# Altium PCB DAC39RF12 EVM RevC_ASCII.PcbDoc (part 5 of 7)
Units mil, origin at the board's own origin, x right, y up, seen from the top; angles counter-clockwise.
Board outline 5071.81 x 2716.54 mil, 16 copper layers (Top Layer, L2 GND1, L3 PWR1, L4 GND2, L5 PWR2, L6 GND3, L7 Ctrl Signal 1, L8 GND4, L9 GND5, L10 Ctrl Signal 2, L11 GND6, L12 PWR3, L13 GND7, L14 PWR4, L15 GND8, Bottom Layer), stack 82.4 mil thick; 596 components, 375 nets, 3310 pads, 1662 vias.
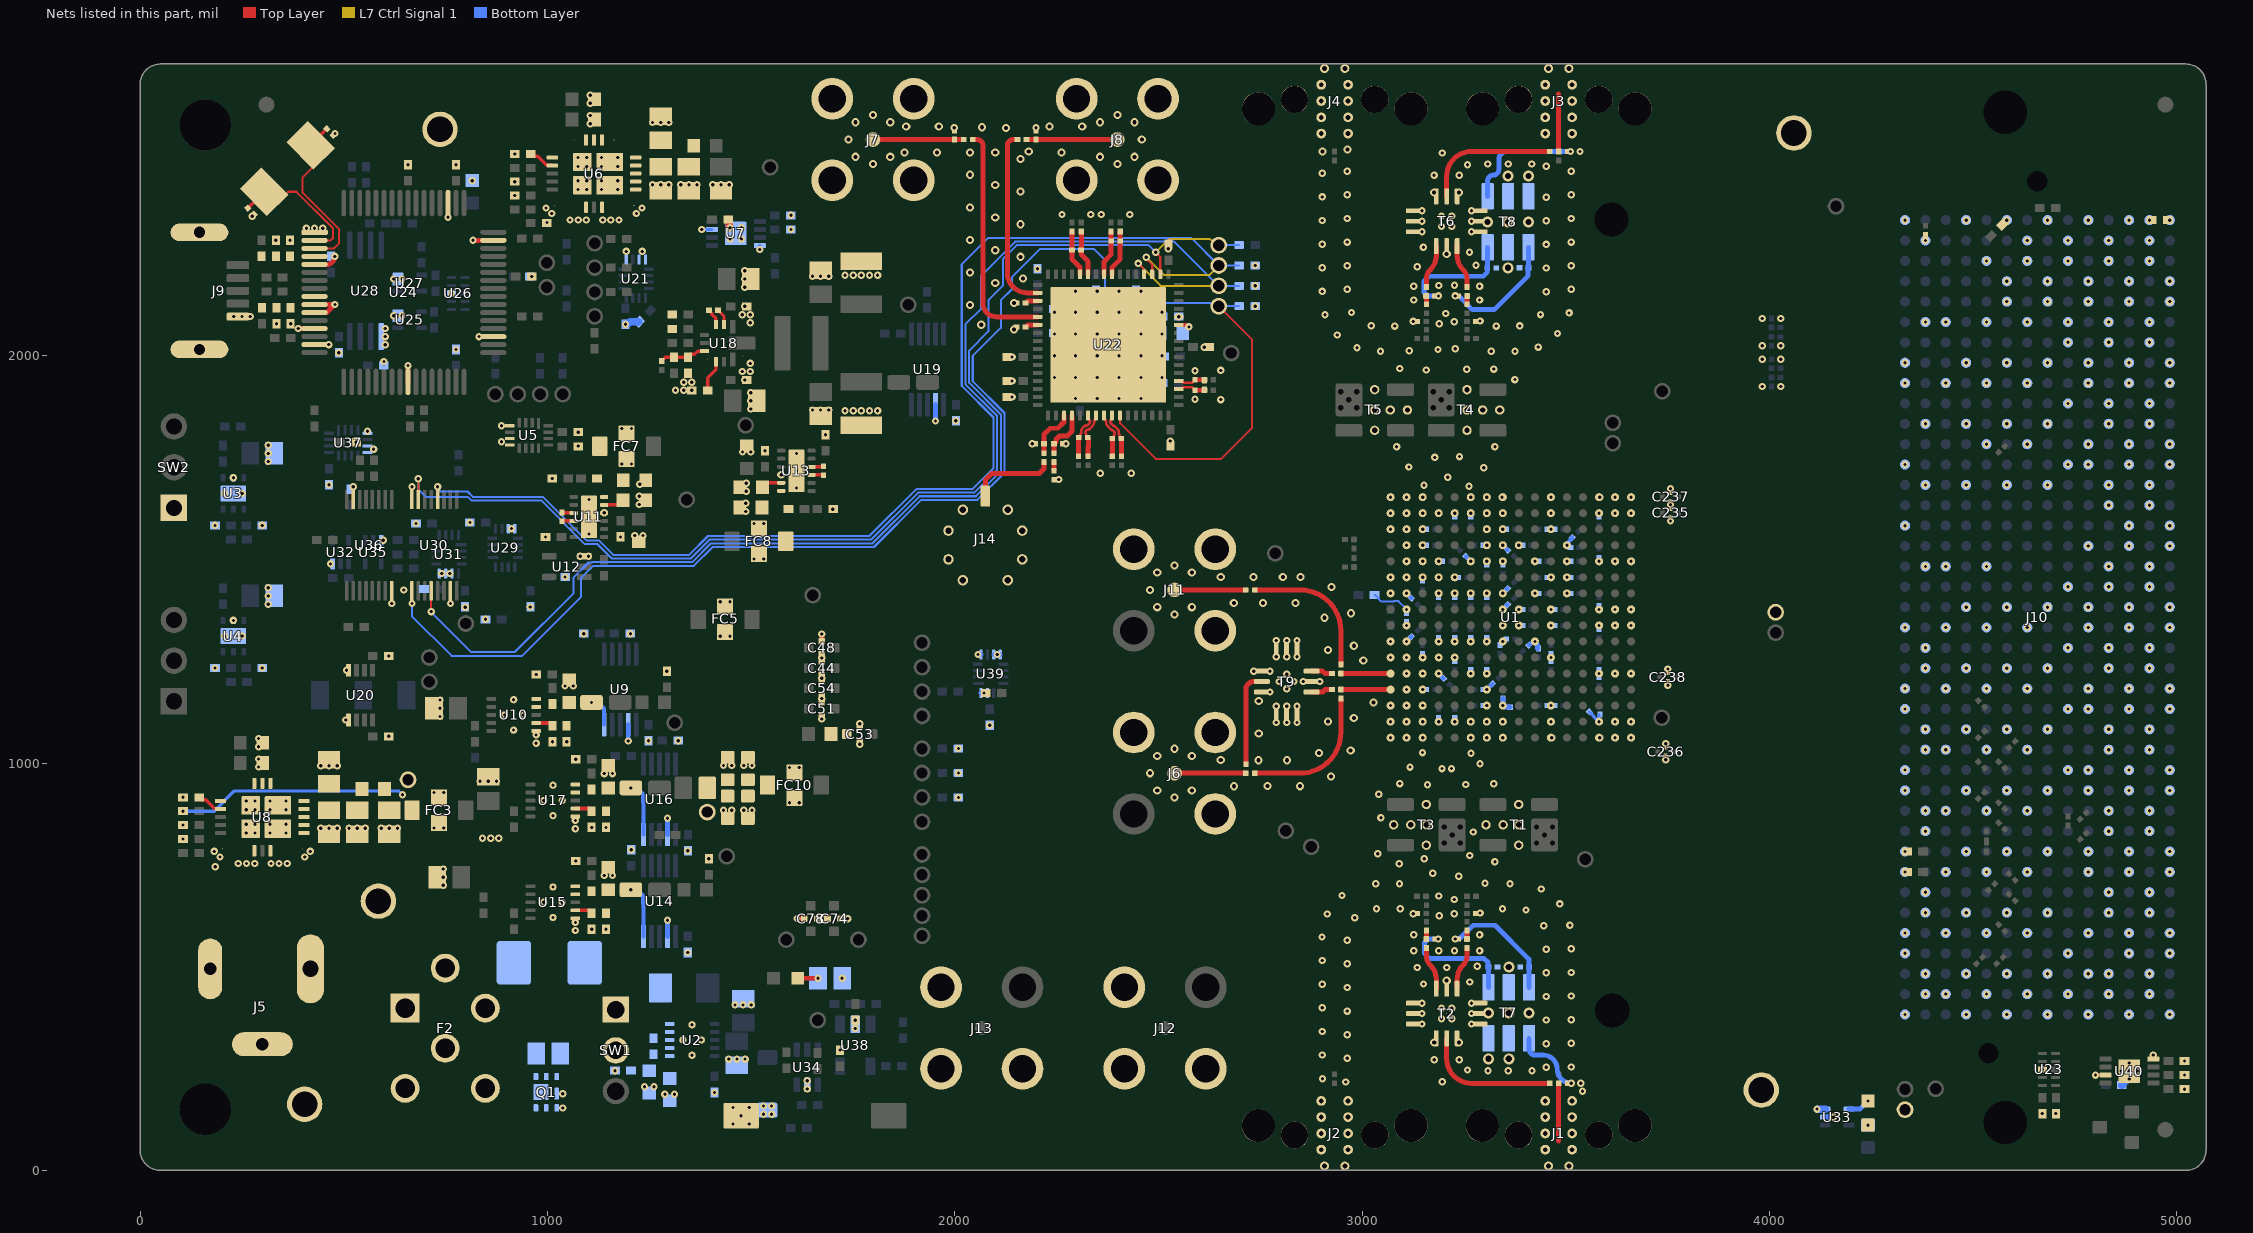
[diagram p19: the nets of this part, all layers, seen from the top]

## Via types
v1: diameter 18, hole 8, Top Layer to Bottom Layer, tented both sides, 1558 vias
v2: diameter 20, hole 10, Top Layer to Bottom Layer, tented both sides, 92 vias
v3: diameter 27, hole 15, Top Layer to Bottom Layer, tented both sides, 12 vias

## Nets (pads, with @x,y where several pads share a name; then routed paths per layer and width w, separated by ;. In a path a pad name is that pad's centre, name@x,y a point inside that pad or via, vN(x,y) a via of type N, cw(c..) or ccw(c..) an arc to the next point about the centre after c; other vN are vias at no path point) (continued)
GND: "J1. "@3350.94,93.75 "J1. "@3482.6,86.25 "J1. "@3614.26,93.75 "J2. "@2800.94,93.75 "J2. "@2932.6,86.25 "J2. "@3064.27,93.75 "J3. "@3350.94,2622.78 "J3. "@3482.6,2630.28 "J3. "@3614.26,2622.78 "J4. "@2800.94,2622.78 "J4. "@2932.6,2630.28 "J4. "@3064.26,2622.78 "J14. " "T1. " "T2. " "T3. " "T4. " "T5. " "T6. " "T9. " "U2. " "U6. "@1016.37,2369.07 "U6. "@1065.09,2364.65 "U6. "@1163.51,2364.65 "U6. "@1212.24,2369.07 "U8. "@202.01,789.43 "U8. "@250.73,785 "U8. "@349.16,785 "U8. "@397.88,789.43 "U10. " "U15. " "U17. " "U18. "@1393.5,1992.3 "U18. "@1479.62,1999.68 "U18. "@1479.62,2062.68 C8.1 C9.1 C10.1 C11.1 C12.1 C13.1 C14.1 C15.1 C16.2 C18.2 C19.1 C20.1 C21.2 C23.1 C24.1 C25.1 C26.1 C27.1 C28.2 C29.1 C30.1 C33.1 C34.1 C35.1 C36.1 C37.1 C38.1 C39.1 C40.1 C41.1 C42.2 C44.2 C45.1 C46.1 C47.1 C48.2 C49.1 C50.1 C51.2 C53.2 C54.2 C55.2 C56.1 C57.1 C59.1 C63.1 C64.1 C65.1 C67.1 C68.1 C69.1 C70.1 C71.1 C72.2 C73.2 C74.2 C75.1 C76.1 C78.2 C79.1 C80.2 C82.1 C83.1 C84.1 C85.1 C86.1 C87.1 C88.1 C89.1 C91.1 C92.1 C93.1 C94.1 C95.2 C96.1 C97.1 C98.1 C108.1 C109.1 C110.1 C111.1 C115.1 C116.1 C117.1 C118.1 C119.1 C120.1 C121.1 C122.1 C123.1 C124.1 C125.1 C126.1 C127.1 C128.1 C144.1 C145.1 C146.1 C147.1 C148.1 C149.1 C150.1 C151.1 C152.1 C153.1 C154.1 C155.2 C158.1 C159.1 C160.1 C161.2 C162.1 C163.1 C164.1 C165.1 C167.2 C168.2 C169.1 C170.1 C171.1 C172.2 C173.1 C174.1 C175.1 C176.1 C177.1 C178.1 C179.1 C180.1 C181.1 C182.1 C183.1 C184.1 C185.1 C186.1 C187.1 C188.1 C189.1 C190.1 C191.1 C192.1 C193.1 C194.1 C195.1 C196.2 C197.2 C198.2 C199.2 C200.2 C201.2 C202.1 C203.1 C204.1 C205.1 C206.1 C207.1 C208.1 C209.1 C210.1 C211.1 C212.1 C213.1 C214.1 C215.1 C216.1 C217.1 C218.1 C219.2 C220.2 C221.2 C222.2 C223.2 C224.2 C225.1 C226.1 C227.1 C228.1 C229.1 C230.1 C231.1 C232.1 C233.1 C234.1 C235.2 C236.2 C237.2 C238.2 C239.1 C240.1 C241.1 C242.1 C243.1 C244.1 C245.1 D1.2 FC3.2 FC5.2 FC7.2 FC8.2 FC10.2 J1.2 J1.3 J1.4 J2.2 J2.3 J2.4 J3.2 J3.3 J3.4 J4.2 J4.3 J4.4 J6.2 J6.3 J6.4 J7.2 J7.3 J7.4 J7.5 J8.2 J8.3 J8.4 J8.5 J9.5 J9.S1 J9.S2 J10.A1 J10.A4 J10.A5 J10.A8 J10.A9 J10.A12 J10.A13 J10.A16 J10.A17 J10.A20 J10.A21 J10.A24 J10.A25 J10.A28 J10.A29 J10.A32 J10.A33 J10.A36 J10.A37 J10.A40 J10.B2 J10.B3 J10.B6 J10.B7 J10.B10 J10.B11 J10.B14 J10.B15 J10.B18 J10.B19 J10.B22 J10.B23 J10.B26 J10.B27 J10.B30 J10.B31 J10.B34 J10.B35 J10.B38 J10.B39 J10.C1 J10.C4 J10.C5 J10.C8 J10.C9 J10.C12 J10.C13 J10.C17 J10.C20 J10.C21 J10.C24 J10.C25 J10.C28 J10.C29 J10.C32 J10.C33 J10.C36 J10.C38 J10.C40 J10.D2 J10.D3 J10.D6 J10.D7 J10.D10 J10.D13 J10.D19 J10.D22 J10.D25 J10.D28 J10.D37 J10.D39 J10.E1 J10.E4 J10.E5 J10.E8 J10.E11 J10.E14 J10.E20 J10.E23 J10.E26 J10.E29 J10.E32 J10.E35 J10.E38 J10.E40 J10.F2 J10.F3 J10.F6 J10.F9 J10.F12 J10.F21 J10.F24 J10.F27 J10.F30 J10.F33 J10.F36 J10.F39 J10.G1 J10.G4 J10.G5 J10.G8 J10.G11 J10.G14 J10.G20 J10.G23 J10.G26 J10.G29 J10.G32 J10.G35 J10.G38 J10.G40 J10.H3 J10.H6 J10.H9 J10.H12 J10.H18 J10.H21 J10.H24 J10.H27 J10.H30 J10.H33 J10.H36 J10.H39 J10.J1 J10.J8 J10.J11 J10.J14 J10.J20 J10.J23 J10.J26 J10.J29 J10.J32 J10.J35 J10.J38 J10.J40 J10.K6 J10.K9 J10.K18 J10.K21 J10.K24 J10.K27 J10.K30 J10.K33 J10.K36 J10.K39 J10.L2 J10.L6 J10.L11 J10.L14 J10.L18 J10.L22 J10.L23 J10.L26 J10.L27 J10.L30 J10.L31 J10.L34 J10.L35 J10.L38 J10.L39 J10.M1 J10.M8 J10.M9 J10.M13 J10.M16 J10.M21 J10.M24 J10.M25 J10.M28 J10.M29 J10.M32 J10.M33 J10.M36 J10.M37 J10.M40 J10.Y1 J10.Y4 J10.Y5 J10.Y8 J10.Y9 J10.Y12 J10.Y13 J10.Y16 J10.Y17 J10.Y20 J10.Y21 J10.Y24 J10.Y25 J10.Y28 J10.Y29 J10.Y32 J10.Y33 J10.Y36 J10.Y37 J10.Y40 J10.Z2 J10.Z3 J10.Z6 J10.Z7 J10.Z10 J10.Z11 J10.Z14 J10.Z15 J10.Z18 J10.Z19 J10.Z22 J10.Z23 J10.Z26 J10.Z27 J10.Z30 J10.Z31 J10.Z34 J10.Z35 J10.Z38 J10.Z39 J11.2 J11.3 J11.4 J12.2 J12.3 J12.4 J13.2 J13.3 J13.4 J14.2 PP2.1 PP49.1 Q1.4 Q1.7 R7.1 R8.1 R17.1 R18.1 R22.1 R23.1 R24.1 R27.2 R32.1 R33.1 R34.1 R37.1 R38.1 R40.1 R41.1 R42.1 R43.1 R49.1 R50.1 R51.1 R52.1 R56.1 R57.1 R60.1 R61.1 R63.1 R65.1 R66.1 R68.1 R73.1 R74.1 R75.1 R78.1 R81.1 R82.1 R88.1 R89.1 R90.1 R91.1 R95.1 R103.1 R104.1 R112.1 R113.1 R126.1 R148.1 R155.1 R173.1 R174.1 R175.1 R178.1 R179.1 R180.1 R181.1 R183.2 R184.2 R185.2 R188.2 R189.2 R190.2 SW2.3 SW3.2 T1.5 T2.2 T2.4 T2.5 T2.6 T2.7 T2.9 T2.10 T2.11 T2.12 T3.5 T4.5 T5.5 T6.2 T6.4 T6.5 T6.6 T6.7 T6.9 T6.10 T6.11 T6.12 T7.1 T7.2 T7.5 T8.1 T8.2 T8.5 T9.2 T9.4 T9.5 T9.6 T9.7 T9.9 T9.10 T9.11 T9.12 TP1.1 TP2.1 TP3.1 U1.A1 U1.A2 U1.A3 U1.A6 U1.A9 U1.A10 U1.A11 U1.A14 U1.A15 U1.A16 U1.B1 U1.B2 U1.B3 U1.B6 U1.B9 U1.B10 U1.B11 U1.B12 U1.B13 U1.B14 U1.B15 U1.B16 U1.C6 U1.C9 U1.C10 U1.C14 U1.C15 U1.C16 U1.D10 U1.D14 U1.D15 U1.E1 U1.E2 U1.E3 U1.E10 U1.E11 U1.E13 U1.E14 U1.E15 U1.F6 U1.F12 U1.F13 U1.F14 U1.F15 U1.F16 U1.G7 U1.G9 U1.G10 U1.G11 U1.G12 U1.G13 U1.G15 U1.G16 U1.H1 U1.H2 U1.H3 U1.H6 U1.H8 U1.H9 U1.H15 U1.J1 U1.J2 U1.J3 U1.J6 U1.J8 U1.J9 U1.K5 U1.K7 U1.K9 U1.K10 U1.K11 U1.K12 U1.K13 U1.K15 U1.K16 U1.L5 U1.L6 U1.L12 U1.L13 U1.L14 U1.L15 U1.L16 U1.M1 U1.M2 U1.M3 U1.M5 U1.M7 U1.M9 U1.M10 U1.M11 U1.M13 U1.M14 U1.M15 U1.N5 U1.N8 U1.N9 U1.N10 U1.N14 U1.N15 U1.P6 U1.P9 U1.P10 U1.P14 U1.P15 U1.P16 U1.R1 U1.R2 U1.R3 U1.R6 U1.R9 U1.R10 U1.R11 U1.R12 U1.R13 U1.R14 U1.R15 U1.R16 U1.T1 U1.T2 U1.T3 U1.T6 U1.T9 U1.T10 U1.T11 U1.T14 U1.T15 U1.T16 U2.11 U3.5 U3.7@207.31,1662.04 U3.7@228.97,1662.04 U3.7@250.62,1662.04 U4.5 U4.7@207.31,1312.04 U4.7@228.97,1312.04 U4.7@250.62,1312.04 U5.5 U5.7 U5.8 U6.3 U6.5 U6.8 U6.9 U6.16 U6.17 U6.20 U6.25 U6.26 U6.28 U7.4 U7.7 U7.9 U8.3 U8.5 U8.8 U8.9 U8.16 U8.17 U8.20 U8.25 U8.26 U8.28 U9.7 U10.6 U10.11 U11.4 U11.13 U12.3 U13.4 U13.13 U14.7 U15.6 U15.11 U16.7 U17.6 U17.11 U19.7 U20.4 U20.5 U21.5 U21.7 U21.8 U22.65 U23.3@4669.81,247.98 U24.1 U24.5 U24.10 U24.11 U24.13 U24.15 U24.25 U24.35 U24.47 U24.51 U25.2 U25.3 U26.3@764.51,2153.25 U27.2 U27.3 U28.5 U29.7 U29.8 U30.8 U30.15 U31.6 U31.7 U31.8 U32.3 U33.2 U33.3 U34.2 U35.3 U36.8 U36.15 U37.5 U37.7 U37.8 U38.2 U39.5 U39.7 U39.8 U39.15 U39.16 U40.4 U40.7 U40.9 | length 3132.7
  Top Layer w5: v1(617.53,1392.03) U36.8@617.53,1423.03 ; U30.8@667.29,1647.44 v1(667.29,1678.44) ; v1(755.91,2339.97) U24.51@755.91,2374.5 ; v1(761.78,1392.03) U30.15@761.78,1423.03 ; v1(832.13,2047.21) U24.35@866.66,2047.21
  Top Layer w8: v1(290.85,990.35) C30.1@300.85,1000.35 v1(290.85,1010.35) ; v1(290.85,1040.35) C33.1@300.85,1050.35 v1(290.85,1060.35) ; U36.15@523.04,1647.44 v1(523.04,1678.44) ; v1(1105.21,2570) C19.1@1115.21,2580 v1(1105.21,2590) ; v1(1105.21,2620) C29.1@1115.21,2630 v1(1105.21,2640) ; v1(1139.61,724.33) 1139.61,734.33 C75.1@1149.61,744.33 1159.61,734.33 v1(1159.61,724.33) ; v1(1139.61,974.33) 1139.61,984.33 C82.1@1149.61,994.33 1159.61,984.33 v1(1159.61,974.33) ; v2(2144.93,2064.27) 2148.37,2067.72 2148.37,2068.66 2148.9,2068.66 C127.1@2151.2,2070.96 ; v2(2144.93,2129.71) 2150.89,2129.71 C128.1@2151.2,2130.02 ; v1(2189.94,1784.07) R37.1@2197.03,1784.07 ; R91.1@2243.6,1695.98 2243.85,1696.23 2254.67,1696.23 v1(2254.91,1696.47) ; R38.1@2265.65,1784.07 v1(2272.73,1784.07) ; v1(2733.67,1225.9) T9.7@2753.67,1225.9 v1(2773.67,1225.9) ; T9.9@2753.67,1174.72 v1(2773.67,1174.72) ; v1(2789.1,1099.6) T9.10@2789.1,1119.6 v1(2789.1,1139.6) ; v1(2789.1,1261.02) T9.6@2789.1,1281.02 v1(2789.1,1301.02) ; v1(2814.69,1099.6) T9.11@2814.69,1119.6 v1(2814.69,1139.6) ; v1(2814.69,1261.02) T9.5@2814.69,1281.02 v1(2814.69,1301.02) ; v1(2840.28,1099.6) T9.12@2840.28,1119.6 v1(2840.28,1139.6) ; v1(2840.28,1261.02) T9.4@2840.28,1281.02 v1(2840.28,1301.02) ; v1(2855.71,1200.31) T9.2@2875.71,1200.31 v1(2895.71,1200.31) ; T2.6@3126.89,359.67 v1(3146.89,359.67) ; T2.5@3126.89,385.26 v1(3146.89,385.26) ; T2.4@3126.89,410.85 v1(3146.89,410.85) ; T6.12@3126.89,2304.73 v1(3146.89,2304.73) ; T6.11@3126.89,2330.32 v1(3146.89,2330.32) ; T6.10@3126.89,2355.91 v1(3146.89,2355.91) ; v2(3176.88,2401.34) T6.9@3181.88,2401.34 ; v2(3177.01,314.23) T2.7@3182.01,314.23 ; T2.2@3207.6,446.28 v2(3207.6,465.97) ; v2(3207.6,2249.61) T6.2@3207.6,2269.3 ; T6.7@3233.06,2401.34 v2(3238.06,2401.34) ; T2.9@3233.19,314.23 v2(3238.19,314.23) ; v1(3268.31,359.67) T2.10@3288.31,359.67 ; v1(3268.31,385.26) T2.11@3288.31,385.26 ; v1(3268.31,410.85) T2.12@3288.31,410.85 ; v1(3268.31,2304.73) T6.4@3288.31,2304.73 ; v1(3268.31,2330.32) T6.5@3288.31,2330.32 ; v1(3268.31,2355.91) T6.6@3288.31,2355.91 ; v1@3745.31,1008.04 v1(3745.31,1008.2) C236.2@3745.31,1018.04 ; C236.2@3745.31,1037.73 C236.2@3745.31,1037.89 v1(3745.31,1047.89) ; v1@3750.61,1191.1 v1(3750.61,1191.26) C238.2@3750.61,1201.1 ; C238.2@3750.61,1220.78 C238.2@3750.61,1220.94 v1@3750.61,1230.78 ; v1@3757.18,1594.53 C235.2@3757.18,1604.37 C235.2@3757.18,1604.53 ; C235.2@3757.18,1624.22 v1(3757.18,1634.06) C237.2@3757.18,1644.06 C237.2@3757.18,1644.22 ; C237.2@3757.18,1663.9 v1(3757.18,1673.74) v1@3757.18,1673.9 ; v1(4382.81,2283.06) R178.1@4382.81,2297.03 ; R155.1@4571.7,2321.94 v1(4582.81,2333.06) ; v1(4800.24,234.2) U40.7@4825.24,234.2 ; U40.4@4942.49,273.57 v1(4942.49,283.57)
  Top Layer w12: v1(388.16,2066.9) U24.13@428.16,2066.9 ; U24.15@428.16,2027.53 v1(463.16,2027.53) ; U24.11@428.16,2106.27 458.47,2106.27 v1(478.16,2125.95) U24.10@428.16,2125.95 ; U24.5@428.16,2224.38 458.31,2224.38 ccw(c458.31,2244.06) v1(478,2244.06) ; U24.25@657.49,1935.99 v1(657.49,1975.99) ; v1(817.13,2283.43) U24.47@867.13,2283.43 ; v1(1432.17,884.09) 1433.31,882.94 1433.31,872.94 C109.1@1442.17,864.09 1451.02,872.94 1451.02,882.94 v1(1452.17,884.09) ; v1(1432.17,994.33) 1433.31,995.48 1433.31,1005.48 C83.1@1442.17,1014.33 1451.02,1005.48 1451.02,995.48 v1(1452.17,994.33) ; v1(1482.17,884.09) 1483.31,882.94 1483.31,872.94 C111.1@1492.17,864.09 1501.02,872.94 1501.02,882.94 v1(1502.17,884.09) ; v1(1482.17,994.33) 1483.31,995.48 1483.31,1005.48 C110.1@1492.17,1014.33 1501.02,1005.48 1501.02,995.48 v1(1502.17,994.33) ; v1(1673.37,1108.43) C51.2@1673.36,1117.67 ; v1(1766.36,1046.46) C53.2@1766.35,1055.7 ; C53.2@1766.36,1087.21 v1(1766.36,1096.45)
  Top Layer w12.3: v1@3125.55,631.1 R7.1@3135.55,631.1 ; v1(3125.55,2084.47) R17.1@3135.55,2084.47 ; R8.1@3279.66,631.1 v1@3289.66,631.1 ; R18.1@3279.66,2084.47 v1@3289.66,2084.47
  Top Layer w14: v1(1612.72,618.42) C78.2@1630.6,618.42 ; C78.2@1662.1,618.42 C74.2@1687.8,618.42 ; C51.2@1673.36,1149.8 C54.2@1673.36,1167.67 ; C54.2@1673.37,1199.18 v1(1673.37,1208.43) C44.2@1673.36,1217.67 ; C44.2@1673.37,1249.18 v1(1673.37,1258.43) C48.2@1673.36,1267.67 ; C48.2@1673.37,1299.18 v1(1673.37,1317.05) ; C74.2@1719.3,618.42 v1(1737.17,618.42)
  Top Layer w18: C68.1@1443.46,2334.95 1445.43,2334.95 1446.27,2334.11 1446.27,2316.44 U7.9@1448.36,2314.34
  Bottom Layer w5: C150.1@598.43,1975.99 v1(598.43,1985.99) ; v1(3109.18,1338.1) C172.2@3109.18,1346.76 ; v1(3148.55,1180.62) C221.2@3157.21,1180.62 ; v1(3148.55,1259.36) C231.1@3148.55,1268.02 ; C234.1@3148.55,1447.55 v1(3148.55,1456.21) ; v1(3148.55,1534.95) C197.2@3157.21,1534.95 ; v1(3148.55,1574.32) C196.2@3157.21,1574.32 ; v1(3187.92,1101.88) C219.2@3187.92,1110.54 ; v1(3187.92,1298.73) C209.1@3187.92,1307.39 ; C230.1@3187.92,1408.18 v1(3187.92,1416.84) ; v1(3187.92,1495.58) C207.1@3196.58,1495.58 ; v1(3227.29,1101.88) C222.2@3227.29,1110.54 ; v1(3227.29,1298.73) C208.1@3227.29,1307.39 ; C229.1@3227.29,1408.18 v1(3227.29,1416.84) ; v1(3227.29,1456.21) C206.1@3235.95,1456.21 ; C201.2@3227.29,1605.03 v1(3227.29,1613.69) ; v1(3266.66,1219.99) C203.1@3266.66,1228.65 ; v1(3266.66,1298.73) C204.1@3266.66,1307.39 ; C205.1@3266.66,1408.18 v1(3266.66,1416.84) ; C200.2@3266.66,1605.03 v1(3266.66,1613.69) ; C223.2@3297.37,1141.25 v1(3306.03,1141.25) ; C224.2@3297.37,1180.62 v1(3306.03,1180.62) ; C199.2@3297.37,1534.95 v1(3306.03,1534.95) ; v1(3306.03,1219.99) C225.1@3306.03,1228.65 ; v1(3306.03,1298.73) C226.1@3306.03,1307.39 ; C227.1@3306.03,1408.18 v1(3306.03,1416.84) ; C228.1@3306.03,1486.92 v1(3306.03,1495.58) ; v1(3345.4,1298.73) C184.1@3354.06,1298.73 ; C179.1@3345.4,1486.92 v1(3345.4,1495.58) ; v1(3345.4,1574.32) C218.1@3354.06,1574.32 ; v1(3384.77,1338.1) C211.1@3393.43,1338.1 ; v1(3384.77,1377.47) C177.1@3393.43,1377.47 ; v1(3384.77,1534.95) C215.1@3393.43,1534.95 ; v1(3424.14,1416.84) C186.1@3432.8,1416.84 ; v1(3424.14,1495.58) C178.1@3432.8,1495.58 ; C193.1@3454.85,1141.25 v1(3463.51,1141.25) C191.1@3472.17,1141.25 ; C213.1@3454.85,1456.21 v1(3463.51,1456.21) ; C182.1@3454.85,1574.32 v1(3463.51,1574.32) C217.1@3472.17,1574.32 ; R148.1@3463.51,1250.7 v1(3463.51,1259.36) C176.1@3463.51,1268.02 ; v1(3463.51,1338.1) C212.1@3472.17,1338.1 ; v1(3463.51,1377.47) C185.1@3472.17,1377.47 ; v1(3502.88,1416.84) C242.1@3511.54,1416.84 ; v1(3502.88,1456.21) C243.1@3511.54,1456.21 ; v1(3502.88,1495.58) C241.1@3511.54,1495.58 ; v1(3502.88,1534.95) C244.1@3511.54,1534.95 ; C195.1@3581.62,1211.33 v1(3581.62,1219.99) C190.1@3581.62,1228.65 ; C189.1@3581.62,1329.44 v1(3581.62,1338.1) ; v1(3581.62,1377.47) C192.1@3581.62,1386.13 ; v1(3581.62,1495.58) C180.1@3581.62,1504.24 ; C216.1@3581.62,1605.03 v1(3581.62,1613.69)
  Bottom Layer w8: v1(1379.09,2310.27) U7.7@1404.09,2310.27 ; v1(1521.34,2260.9) U7.4@1521.34,2270.9 ; C174.1@3557.84,1125.66 3580.09,1103.41 v1(3581.62,1101.88) C194.1@3581.62,1119.2
  Bottom Layer w10: v1(3109.18,1298.73) C232.1@3121.07,1310.62 ; v1(3109.18,1416.84) C233.1@3121.07,1404.95 ; v1(3187.92,1219.99) C220.2@3199.81,1208.1 ; v1@3227.29,1257.79 v1(3227.29,1259.36) ; C198.2@3254.77,1507.47 v1(3266.66,1495.58) ; v1(3306.03,1180.62) C240.1@3319.92,1194.51 ; v1(3345.4,1377.47) C187.1@3357.29,1389.36 ; v1(3345.4,1416.84) C214.1@3357.29,1428.73 ; v1(3345.4,1534.95) C188.1@3357.29,1523.06 ; C210.1@3409.36,1289.95 3411.19,1289.95 3418.44,1297.2 v1@3422.61,1297.2 ; v1(3502.88,1534.95) 3504.41,1536.48 3504.41,1540.94 3515.66,1552.19 C181.1@3515.66,1553.73 ; v1@3580.09,1103.41 v1(3581.62,1101.88)
  Bottom Layer w12: v1(1198.26,1054.56) U9.7@1198.26,1094.56 ; U14.7@1294.76,574.59 v1(1294.76,614.59) ; U16.7@1294.76,824.59 v1(1294.76,864.59) ; v1(1952.76,1840.18) U19.7@1952.76,1880.18 ; v1(2056.82,1266.67) U39.5@2064.32,1266.67 ; U39.16@2064.32,1172.18 v1(2071.82,1172.18) U39.15@2080.07,1172.18 ; U39.7@2095.82,1266.67 v1(2104.07,1266.67) U39.8@2111.57,1266.67 ; C239.1@3345.4,1158.58 v1(3345.4,1141.25) 3347.02,1141.25 3350.72,1137.55 3362.42,1137.55 C173.1@3362.72,1137.25 ; v1(3424.14,1298.73) 3424.14,1297.11 3430.44,1290.81 3430.44,1281.71 C175.1@3430.74,1281.41 ; U33.2@4136.74,131 v1(4156.74,131)
  Bottom Layer w18: v1(1191.41,2077.47) 1191.41,2079.43 1192.25,2080.28 1199.7,2080.28 1202.79,2083.37 1220.95,2083.37 1222.34,2081.98 1223.54,2081.98 C70.1@1224.93,2083.37 ; U22.65@2296.16,1894.86 2303.19,1901.89 2306.73,1901.89 2307.58,1902.73 C124.1@2307.58,1904.7 ; C116.1@2445.37,2160.61 ccw(c2447.34,2160.61) 2447.34,2158.64 U22.65@2456.79,2158.64 ; U22.65@2508.36,1946.43 2508.36,1935.49 ccw(c2510.27,1935.49) R112.1@2510.27,1933.57 ; U22.65@2508.36,2107.06 cw(c2508.36,2105.1) 2510.33,2105.1 C145.1@2510.33,2096.65 ; v1(4116.74,150.69) U33.3@4136.74,150.69 ; C245.1@4864.61,209.51 4866.58,209.51 4867.42,210.36 4867.42,212.32 4879.45,224.36 U40.9@4883.43,224.36
  other v1: 1455.41,114.36 1495.41,114.36 1475.41,134.36 1530.24,138.29 1550.24,138.29 4669.81,139.64 4702.69,139.64 1037.79,153.46 1455.41,154.36 1495.41,154.36 1530.24,158.29 1550.24,158.29 1288.27,186.85 1311.73,186.85 1037.79,188.46 1410.24,191.58 3540.82,194.58 5018.86,199.51 1637.78,200.32 1238.27,205.63 1261.73,205.63 3536.57,214.04 2960.02,217.4 3196.9,217.69 1637.78,220.32 2902.56,225.34 5018.86,234.2 3308.83,244.78 3358.83,244.78 3416.83,244.78 1165.75,245 3258.83,246.78 4669.81,247.98 3451.86,253.25 3513.34,254.16 5018.86,268.88 3176.79,272.09 3238.47,272.09 1445.24,273.45 1465.24,273.45 1485.24,273.45 2963.34,275.31 2901.86,283.33 1718.33,295.62 3451.86,311.25 3513.34,312.16 2963.34,333.31 2901.86,341.33 1755.73,348.61 1755.73,368.61 3451.86,369.25 3513.34,370.16 3194.87,372.53 3220.33,372.53 4332.81,383.06 4482.81,383.06 4582.81,383.06 4682.81,383.06 4782.81,383.06 4882.81,383.06 4982.81,383.06 2963.34,391.31 3194.87,397.98 3220.33,397.98 2901.86,399.33 1460.24,406.56 1480.24,406.56 1500.24,406.56 3451.86,427.25 3513.34,428.16 4382.81,433.06 4432.81,433.06 4532.81,433.06 4632.81,433.06 4732.81,433.06 4832.81,433.06 4932.81,433.06 2963.34,449.31 2901.86,457.33 3150.48,457.75 3264.31,462.93 1723.37,471.85 4382.81,483.06 4482.81,483.06 4582.81,483.06 4682.81,483.06 4782.81,483.06 4832.81,483.06 4932.81,483.06 3451.86,485.25 3513.34,486.16 3135.15,498.54 3207.76,498.54 3282.34,501.13 2963.34,507.31 2901.86,515.33 4332.81,533.06 4732.81,533.06 4882.81,533.06 4982.81,533.06 1344.42,535.22 3126.83,539.32 3188.37,539.32 3226.84,539.32 3288.38,539.32 3451.86,543.25 3513.34,544.16 2963.34,565.31 2901.66,573.33 3126.83,578.66 3288.38,578.66 4332.81,583.06 4432.81,583.06 4532.81,583.06 4632.81,583.06 4782.81,583.06 4882.81,583.06 4982.81,583.06 1068.61,589.09 1108.61,592.32 1143.61,592.32 3445.95,600.95 3510.04,602.07 1068.61,609.09 1674.95,618.42 2981.97,620.23 3189.15,625.22 2914.63,629.86 3125.55,630.1 3226.05,630.35 3289.66,632.1 4382.81,633.06 4482.81,633.06 4582.81,633.06 4682.81,633.06 4832.81,633.06 4932.81,633.06 3402.45,639.31 3035.48,642.61 3093.48,642.61 3344.55,642.61 3485.12,654.44 3226.44,665.08 3188.37,673.85 2950.76,675.23 4382.81,683.06 4832.81,683.06 4932.81,683.06 3440.04,690.94 744.43,700.09 3033.65,704.09 3091.65,704.09 3363.14,704.09 3301.74,705.47 744.43,720.09 3237.31,722.05 3173.2,729.83 4332.81,733.06 4432.81,733.06 4532.81,733.06 4632.81,733.06 4782.81,733.06 4882.81,733.06 4982.81,733.06 744.43,740.09 184.14,745.98 3091.17,752.85 241.12,753.6 261.12,753.6 281.12,753.6 321.12,753.6 341.12,753.6 361.12,753.6 3325.92,758.18 1069.24,759.61 1396.1,765.58 3152.22,765.34 195.95,769.65 403.94,769.65 3264.13,773.48 3038.58,777.31 182.23,783.36 417.66,783.36 4332.81,783.06 4482.81,783.06 4582.81,783.06 4682.81,783.06 4782.81,783.06 4882.81,783.06 4982.81,783.06 1344.45,785.22 1205.71,787.19 105.4,813.98 840.64,815.35 860.64,815.35 880.64,815.35 3272.49,830.87 4382.81,833.06 4832.81,833.06 4932.81,833.06 1068.61,839.09 443.65,840.35 463.65,840.35 483.65,840.35 512.96,840.35 532.96,840.35 552.96,840.35 591.7,840.35 611.7,840.35 631.7,840.35 1108.61,842.32 1143.61,842.32 105.4,847.98 1068.61,859.09 3046.08,866.07 4382.81,883.06 4432.81,883.06 4532.81,883.06 4632.81,883.06 4832.81,883.06 4932.81,883.06 2008.85,915.8 105.4,915.98 3040.57,923.8 4332.81,933.06 4482.81,933.06 4582.81,933.06 4682.81,933.06 4782.81,933.06 4882.81,933.06 4982.81,933.06 3160.52,947.22 3254.51,947.4 3092.42,949.78 3322.83,949.64 834.64,955.46 854.64,955.46 874.64,955.46 2008.85,975.8 4332.81,983.06 4732.81,983.06 4782.81,983.06 4882.81,983.06 4982.81,983.06 3196.01,986.64 3219.44,986.64 3117.32,990.34 443.65,993.42 463.65,993.42 483.65,993.42 3289.53,998.6 1069.24,1009.61 3267.29,1024.55 3148.16,1025.9 4382.81,1033.06 4432.81,1033.06 4532.81,1033.06 4632.81,1033.06 4832.81,1033.06 4932.81,1033.06 2008.85,1035.8 972.11,1049.09 1012.11,1052.32 1047.11,1052.32 1247.95,1055.19 1321.32,1055.19 3069.81,1062.51 3109.18,1062.51 3148.55,1062.51 3266.66,1062.51 3306.03,1062.51 3345.4,1062.51 3465.51,1062.51 3583.62,1062.51 3620.99,1062.51 3660.36,1062.51 610.14,1065.84 972.11,1069.09 4382.81,1083.06 4482.81,1083.06 4582.81,1083.06 4682.81,1083.06 4832.81,1083.06 4932.81,1083.06 2085.82,1092.81 3069.81,1101.88 3109.18,1101.88 3148.55,1101.88 3266.66,1101.88 3306.03,1101.88 3345.4,1101.88 3463.51,1101.88 3620.99,1101.88 3660.36,1101.88 504.71,1105.84 736.35,1114.75 4332.81,1133.06 4732.81,1133.06 4782.81,1133.06 4882.81,1133.06 4982.81,1133.06 736.35,1134.75 3069.81,1141.25 3109.18,1141.25 3148.55,1141.25 736.35,1154.75 1673.37,1158.43 3109.18,1180.62 2814.69,1182.31 4332.81,1183.06 4432.81,1183.06 4532.81,1183.06 4632.81,1183.06 4782.81,1183.06 4882.81,1183.06 4982.81,1183.06 1043.11,1189.29 1063.11,1189.29 2796.69,1200.31 2832.69,1200.31 972.74,1217.64 2814.69,1218.31 3109.18,1219.99 3148.55,1219.99 3620.99,1219.99 3660.36,1219.99 1293.13,1225.54 506.71,1227.88 3750.61,1230.94 183.69,1233.65 299.83,1233.65 4382.81,1233.06 4482.81,1233.06 4582.81,1233.06 4682.81,1233.06 4832.81,1233.06 4932.81,1233.06 3069.81,1259.36 3109.18,1259.36 3187.92,1259.36 610.14,1262.88 4382.81,1283.06 4732.81,1283.06 4832.81,1283.06 4932.81,1283.06 3069.81,1298.73 1088.93,1317.79 1203.65,1317.79 4332.81,1333.06 4432.81,1333.06 4532.81,1333.06 4632.81,1333.06 4782.81,1333.06 4882.81,1333.06 4982.81,1333.06 3345.4,1338.1 3620.99,1338.1 3660.36,1338.1 228.97,1350.42 847.88,1353.03 3620.99,1377.47 3660.36,1377.47 797.9,1382.72 958.05,1383.51 4482.81,1383.06 4582.81,1383.06 4682.81,1383.06 4782.81,1383.06 4882.81,1383.06 4982.81,1383.06 314.36,1390.42 314.36,1410.42 3069.81,1416.84 647,1425.15 314.36,1430.42 4732.81,1433.06 4832.81,1433.06 4932.81,1433.06 3069.81,1456.21 3109.18,1456.21 3187.92,1456.21 1043.32,1457.01 740.34,1465.55 760.08,1465.55 4382.81,1483.06 4432.81,1483.06 4532.81,1483.06 4832.81,1483.06 4932.81,1483.06 467.57,1489.17 3109.18,1495.58 3148.55,1495.58 3620.99,1495.58 3660.36,1495.58 1080.56,1508.19 1100.56,1508.19 4782.81,1533.06 4882.81,1533.06 4982.81,1533.06 3109.18,1534.95 596.94,1547.44 995.17,1555.42 1179.34,1555.42 1214.35,1558.61 1234.35,1558.61 3069.81,1574.32 3109.18,1574.32 3306.03,1574.32 911.82,1575.78 183.69,1583.65 299.83,1583.65 4332.81,1583.06 4882.81,1583.06 4982.81,1583.06 677.17,1588.38 809.55,1590.72 3757.18,1594.37 3069.81,1613.69 3109.18,1613.69 3148.55,1613.69 3187.92,1613.69 3306.03,1613.69 3345.4,1613.69 3463.51,1613.69 3620.99,1613.69 3660.36,1613.69 1139.34,1614.48 1486.95,1617.76 1700.41,1623.59 4832.81,1633.06 4932.81,1633.06 1225.36,1634.99 1486.95,1637.76 3069.81,1653.06 3109.18,1653.06 3148.55,1653.06 3266.66,1653.06 3306.03,1653.06 3343.4,1653.06 3463.51,1653.06 3583.62,1653.06 3620.99,1653.06 3660.36,1653.06 1225.36,1654.99 1487.93,1667.45 3262.57,1679.99 3151.89,1682.45 463.71,1683.43 4382.81,1683.06 4482.81,1683.06 4582.81,1683.06 4682.81,1683.06 4832.81,1683.06 4932.81,1683.06 1226.35,1684.68 1487.93,1687.45 1011.88,1698.85 228.97,1700.42 3210.2,1702.16 1573.96,1707.96 2357.04,1711.47 2433.16,1711.47 3298.68,1725.38 3114.84,1727.08 4332.81,1733.06 4732.81,1733.06 4782.81,1733.06 4882.81,1733.06 4982.81,1733.06 314.36,1740.42 3178.28,1750.59 3238.95,1752.62 314.36,1760.42 1478.95,1763.83 1498.95,1763.83 1533.96,1767.02 573.19,1770.67 3084.62,1776.58 3325.92,1776.58 1075.46,1778.47 314.36,1780.42 4532.81,1783.06 4632.81,1783.06 4782.81,1783.06 4882.81,1783.06 4982.81,1783.06 530.82,1787.79 887.36,1788.84 2529.03,1790.96 1682.76,1806.39 1075.46,1812.47 558.19,1815.04 887.36,1828.21 4382.81,1833.06 4482.81,1833.06 4582.81,1833.06 4682.81,1833.06 4832.81,1833.06 4932.81,1833.06 2002.44,1840.81 1730.46,1864.88 1750.46,1864.88 1770.46,1864.88 1790.46,1864.88 1810.46,1864.88 1650.46,1867.12 1670.46,1867.12 1690.46,1867.12 1499.15,1869.53 4732.81,1883.06 4832.81,1883.06 4932.81,1883.06 1499.15,1889.53 2652.7,1892.48 2589.7,1893.43 2140.69,1898.8 1499.15,1909.53 1314.3,1915.42 1334.3,1915.42 1354.3,1915.42 3982,1924.51 4028,1924.51 4332.81,1933.06 4432.81,1933.06 4532.81,1933.06 4632.81,1933.06 4782.81,1933.06 4882.81,1933.06 4982.81,1933.06 1334.3,1935.42 1354.3,1935.42 2140.69,1938.17 1484.46,1940.83 3375.04,1941.6 1478.07,1961.36 1498.07,1961.36 2589.7,1963.21 2652.7,1964.17 3157.14,1965.27 3257.08,1967.11 3323.11,1967.42 3092.52,1968.81 1498.07,1981.36 4332.81,1983.06 4482.81,1983.06 4582.81,1983.06 4682.81,1983.06 4782.81,1983.06 4882.81,1983.06 4982.81,1983.06 3982,1991.6 4028,1991.6 2140.69,1997.22 487.77,2007.84 3045.04,2011.48 3317.17,2011.48 3375.17,2011.48 3115.81,2012.35 775.6,2015.36 3186.31,2015.4 3228.66,2017.66 2987.6,2019.54 2612.26,2021.28 3432.31,2021.43 3982,2024.51 4028,2024.51 601.54,2027.21 4732.81,2033.06 4832.81,2033.06 4932.81,2033.06 601.54,2047.21 2938.88,2051 3479.73,2054.82 601.54,2067.21 3080.2,2072.97 3329.09,2072.97 3387.09,2073.45 3022.21,2074.05 334.53,2078.55 369.53,2078.55 3189.15,2078.59 1498.07,2081 3226.05,2083.72 4382.81,2083.06 4432.81,2083.06 4532.81,2083.06 4632.81,2083.06 4732.81,2083.06 4832.81,2083.06 4932.81,2083.06 3289.66,2085.47 3982,2091.6 4028,2091.6 230.16,2096.42 250.16,2096.42 270.16,2096.42 622.86,2098.39 642.86,2098.39 2908.74,2100.56 1478.07,2101 1498.07,2101 3438.03,2101.18 3205.47,2103.72 3508.1,2105.41 2973.91,2106.16 1484.46,2121.53 2737.31,2121.79 4582.81,2133.06 4682.81,2133.06 4782.81,2133.06 4882.81,2133.06 4982.81,2133.06 3126.83,2136.92 3288.38,2136.92 764.51,2153.25 3451.86,2157.51 2901.99,2158.16 2963.47,2163.21 3513.34,2163.18 1484.3,2168.58 2737.31,2171.79 3126.83,2171.01 3288.38,2171.01 3188.21,2172.58 3226.95,2173.28 4582.81,2183.06 4682.81,2183.06 4782.81,2183.06 4882.81,2183.06 4982.81,2183.06 622.86,2188.41 642.86,2188.41 1484.3,2188.58 961.5,2195.01 1650.46,2195.23 1670.46,2195.23 1690.46,2195.23 1730.46,2197.48 1750.46,2197.48 1770.46,2197.48 1790.46,2197.48 1810.46,2197.48 1484.3,2208.58 2203.25,2213.76 3451.86,2215.51 2901.99,2216.16 3135.1,2218.85 2737.31,2221.79 2963.47,2221.21 3513.34,2221.18 3279.56,2222.59 4532.81,2233.06 4632.81,2233.06 4732.81,2233.06 4832.81,2233.06 4932.81,2233.06 3263.77,2254.18 1193.59,2256.32 1232.96,2256.32 2524.11,2262.54 3150.37,2266.69 3451.86,2273.51 2901.99,2274.16 2963.47,2279.21 3513.34,2279.18 333.16,2283.43 368.16,2283.43 4632.81,2283.06 4732.81,2283.06 4832.81,2283.06 4932.81,2283.06 1597.71,2310.27 408.16,2313.12 428.16,2313.12 448.16,2313.12 3194.87,2317.59 3220.33,2317.59 998.74,2327.16 3451.86,2331.51 2901.99,2332.16 1055.48,2333.25 1075.48,2333.25 1095.48,2333.25 1135.48,2333.25 1155.48,2333.25 1175.48,2333.25 4332.81,2333.06 4482.81,2333.06 4682.81,2333.06 4782.81,2333.06 4882.81,2333.06 4982.81,2333.06 2963.47,2337.21 3513.34,2337.18 275.4,2342.78 3194.87,2343.05 3220.33,2343.05 1597.71,2344.95 2263.29,2347.02 2333.74,2347.02 2359.69,2347.02 2429.64,2347.02 1010.31,2349.29 1218.3,2349.29 996.59,2363.01 1232.02,2363.01 3451.86,2389.51 2901.99,2390.16 919.76,2393.63 2963.47,2395.21 3513.34,2395.18 1258,2420 1278,2420 1298,2420 1327.32,2420 1347.32,2420 1367.32,2420 1406.06,2420 1426.06,2420 1446.06,2420 919.76,2427.63 815.28,2430.09 3176.66,2443.49 3238.34,2443.49 2901.99,2448.16 2963.47,2453.21 3513.34,2453.18 3451.86,2465.24 3258.7,2468.79 657.49,2469.34 775.6,2469.34 3308.7,2470.79 3358.7,2470.79 3416.7,2470.79 919.76,2495.63 3196.77,2497.89 3534.74,2501.53 478.45,2545.83 1998.93,2560.11 2199.19,2560.11 1258,2573.07 1278,2573.07 1298,2573.07
  other v2: 2539.47,915.31 2497.04,932.88 2581.89,932.88 2685.72,943.27 2767.27,943.55 2847.27,943.44 2923.6,967.39 2479.47,975.31 2652.89,1007.35 2745.99,1007.22 2815.9,1007.07 2497.04,1017.73 2581.89,1017.73 2893.79,1025.3 2971.95,1031.13 2539.47,1035.31 2746.23,1072.93 2916,1102.16 2979.52,1110.77 3028.24,1148.86 2746.23,1152.93 3002.91,1251.75 2916,1277.38 2979.52,1288.3 2907.79,1356.96 2539.47,1365.31 2972.56,1368 2497.04,1382.88 2581.89,1382.88 2684.99,1393.27 2756.65,1393.52 2836.65,1393.55 2479.47,1425.31 2924.77,1432.16 2652.89,1457.35 2732.89,1457.35 2805.24,1457.07 2848.75,1457.08 2497.04,1467.73 2581.89,1467.73 2539.47,1485.31 2064.93,2076.27 2037.69,2124.53 2099.29,2179.15 2167.25,2190.19 2037.22,2204.53 2160.91,2243.05 2099.29,2259.15 2037.22,2284.53 2160.91,2323.05 2099.29,2339.15 2037.22,2364.53 2160.91,2403.05 2099.29,2419.15 2037.22,2444.53 1799.06,2470.98 2399.06,2470.98 2160.91,2483.05 1756.64,2488.55 1841.49,2488.55 2356.64,2488.55 2441.49,2488.55 1876.35,2498.94 1956.35,2498.94 2037.69,2498.94 2099.29,2499.15 2261.59,2498.94 2181.63,2501.53 2902.91,2501.17 2964.39,2506.22 1739.06,2530.98 2459.06,2530.98 2126.02,2559.45 2067.05,2561.07 1880.72,2563.02 1960.72,2563.02 2232.81,2563.02 2312.81,2563.02 1756.64,2573.41 1841.49,2573.41 2356.64,2573.41 2441.49,2573.41 1799.06,2590.98 2399.06,2590.98
  other v3: 3310,274.23 3360,274.23 3310,386.83 3360,386.83 3410,386.83 3360,499.43 3358.16,2216.15 3308.16,2328.74 3358.16,2328.74 3408.16,2328.74 3358.16,2441.34 3408.16,2441.34
HSPC-PRSNT-M2C-L: J10.Z1 R181.2
  other v1: 4932.81,2333.06
LMK_C\S\: PP24.1 R182.2 U22.18 U30.12 | length 2964.1
  Top Layer w5: v1(714.53,1372.03) U30.12@714.53,1423.03 ; v1(2493.17,2254.13) 2504.43,2242.88 U22.18@2504.43,2199.98
  L7 Ctrl Signal 1 w5: v1(2493.17,2254.13) 2525.33,2286.29 2627.01,2286.29 2641.51,2271.79 PP24.1@2647.94,2271.79
  Bottom Layer w5: v1(714.53,1372.03) 714.53,1370.95 812.05,1273.43 920.34,1273.43 1064.04,1417.14 1064.04,1455.99 1100.74,1492.69 1108.3,1492.69 1109.06,1493.45 1355.39,1493.45 1401.57,1539.63 1797.92,1539.63 1913.57,1655.28 2051.61,1655.28 2113,1716.67 2113,1855.97 2035.11,1933.86 2035.11,2012.62 2082.34,2059.84 2082.34,2136.86 2117.79,2172.32 2117.79,2237.2 2152.13,2271.54 2475.77,2271.54 v1(2493.17,2254.13) ; PP24.1@2647.94,2271.79 R182.2@2697.94,2271.79
LMK_DCLKOUT4_N: C132.2 R101.2 U22.25 | length 112.5
  Top Layer w12.3: U22.25@2366.63,2199.98 2366.63,2231.77 2384,2249.14 R101.2@2384,2281.98 2384,2303.37 2383.19,2304.19 C132.2@2383.19,2304.98
LMK_DCLKOUT4_P: C131.2 R101.1 U22.24 | length 113.2
  Top Layer w12.3: U22.24@2386.32,2199.98 2386.32,2217.11 2406.05,2236.85 R101.1@2406.05,2281.98 2406.05,2304.89 C131.2@2406.14,2304.98
LMK_DCLKOUT6_N: C134.2 R102.2 U22.28 | length 113.4
  Top Layer w12.3: C134.2@2287.29,2304.98 2287.29,2256.83 2287.58,2256.55 2287.58,2237.11 2307.58,2217.11 U22.28@2307.58,2199.98
LMK_DCLKOUT6_P: C133.2 R102.1 U22.27 | length 112
  Top Layer w12.3: C133.2@2310.47,2304.98 2310.47,2259.33 2310.53,2259.28 2310.53,2248.5 2327.26,2231.77 U22.27@2327.26,2199.98
LMK_DCLKOUT10_N: C138.2 R105.2 U22.55 | length 114.4
  Top Layer w6.3: R105.2@2326.51,1799.07 cw(c2326.51,1800.97) 2325.17,1799.62 2324.15,1800.65 cw(c2327.95,1804.45) 2322.58,1804.45 2322.58,1806.34 ccw(c2319.27,1806.34) 2321.61,1808.68 cw(c2323.95,1811.02) 2320.64,1811.02 2320.64,1812.26 cw(c2326.94,1812.26) 2322.49,1816.71 2322.63,1816.86 cw(c2326.73,1812.77) 2326.73,1818.56 ccw(c2326.73,1824.35) 2330.82,1820.25 2337.35,1826.78 ccw(c2325.51,1838.62) 2342.25,1838.62 cw(c2350.26,1838.62) 2344.6,1844.29 ccw(c2338.94,1849.95) 2346.95,1849.95 U22.55@2346.95,1853.52
  Top Layer w12.3: R105.2@2326.51,1799.07 cw(c2323.76,1796.32) 2327.65,1796.32 2327.65,1776.07 ccw(c2329.55,1774.17) 2326.87,1774.17 C138.2@2326.87,1753.52
LMK_DCLKOUT10_P: C137.2 R105.1 U22.54 | length 114.6
  Top Layer w6.3: R105.1@2304.47,1799.07 ccw(c2304.47,1800.97) 2305.81,1799.62 2306.83,1800.65 ccw(c2303.03,1804.45) 2308.4,1804.45 2308.4,1806.34 cw(c2311.71,1806.34) 2309.37,1808.68 ccw(c2307.03,1811.02) 2310.34,1811.02 2310.34,1814.39 cw(c2321.79,1814.39) 2313.69,1822.49 2318.37,1827.16 ; 2318.37,1827.17 cw(c2322.46,1823.07) 2322.46,1828.86 ccw(c2322.46,1834.65) 2326.56,1830.55 2329.84,1833.83 ccw(c2324.72,1838.94) 2331.95,1838.94 ccw(c2324.73,1838.94) 2329.84,1844.06 2329.61,1844.29 cw(c2335.27,1849.95) 2327.26,1849.95 U22.54@2327.26,1853.52
  Top Layer w12.3: C137.2@2303.91,1753.52 2303.91,1774.17 ccw(c2301.23,1774.17) 2303.13,1776.07 2303.13,1795.84 cw(c2307.7,1795.84) R105.1@2304.47,1799.07
LMK_SCLK: PP21.1 R183.1 U22.19 U30.4 | length 3078.2
  Top Layer w5: U30.4@730.28,1647.44 v1(730.28,1678.44) ; v1(2469.98,2242.29) 2469.98,2238.8 2484.74,2224.04 U22.19@2484.74,2199.98
  L7 Ctrl Signal 1 w5: v1(2469.98,2242.29) 2514.19,2198.08 2624.23,2198.08 PP21.1@2647.94,2221.79
  Bottom Layer w5: v1(730.28,1678.44) 730.28,1674.92 735.05,1670.15 735.05,1669.86 737.98,1666.94 803.74,1666.94 816.74,1653.94 988.48,1653.94 1095.54,1546.87 1108.33,1546.87 1108.52,1547.07 1125.67,1547.07 1161.28,1511.45 1347.94,1511.45 1394.12,1557.63 1790.46,1557.63 1906.11,1673.28 2044.15,1673.28 2095,1724.13 2095,1848.52 2017.11,1926.4 2017.11,2224.31 2082.34,2289.54 2580.2,2289.54 PP21.1@2647.94,2221.79 R183.1@2697.94,2221.79
LMK_SDCLKOUT1_N: C81.2 R35.2 R104.2 U22.4 | length 68.6
  Top Layer w6.3: U22.4@2549.7,1938.17 2556.59,1938.17 2561.28,1933.47 2582.86,1933.47 2586.55,1937.16 2586.55,1938.02 R104.2@2589.7,1941.17
  Top Layer w12.1: R104.2@2589.7,1941.17 C81.2@2612.7,1941.17
LMK_SDCLKOUT1_P: C77.2 R35.1 R103.2 U22.3 | length 68.6
  Top Layer w6.3: U22.3@2549.7,1918.48 2556.59,1918.48 2561.28,1923.17 2582.86,1923.17 2586.55,1919.48 2586.55,1918.63 R103.2@2589.7,1915.48
  Top Layer w12.1: R103.2@2589.7,1915.48 C77.2@2612.7,1915.48
LMK_SDCLKOUT11_N: C140.2 R106.1 U22.57 | length 112.8
  Top Layer w6.3: U22.57@2386.32,1853.52 2386.32,1849.95 cw(c2378.31,1849.95) 2383.97,1844.29 2383.74,1844.06 ccw(c2388.85,1838.94) 2381.62,1838.94 ccw(c2388.85,1838.94) 2383.74,1833.83 2388.85,1828.72 ccw(c2390.55,1830.43) 2390.55,1828.02 cw(c2390.55,1825.62) 2392.24,1827.32 2399.53,1820.04 cw(c2391.43,1811.94) 2402.88,1811.94 2402.88,1808.57 ccw(c2406.19,1808.57) 2403.85,1806.23 cw(c2401.51,1803.89) 2404.82,1803.89 2404.82,1802 ccw(c2410.2,1802) 2406.39,1798.2 2407.41,1797.18 ccw(c2408.76,1798.52) R106.1@2408.76,1796.62
  Top Layer w12.3: R106.1@2408.76,1796.62 cw(c2406.57,1794.43) 2409.66,1794.43 C140.2@2409.66,1753.52
LMK_SDCLKOUT11_P: C139.2 R106.2 U22.56 | length 112.4
  Top Layer w6.3: U22.56@2366.63,1853.52 2366.63,1849.95 ccw(c2374.64,1849.95) 2368.98,1844.29 cw(c2363.31,1838.62) 2371.32,1838.62 ccw(c2388.07,1838.62) 2376.23,1826.78 2384.58,1818.43 ccw(c2386.28,1820.13) 2386.28,1817.72 cw(c2386.28,1815.32) 2387.98,1817.02 2390.74,1814.26 cw(c2386.28,1809.81) 2392.58,1809.81 2392.58,1808.57 cw(c2389.28,1808.57) 2391.61,1806.23 ccw(c2393.95,1803.89) 2390.65,1803.89 2390.65,1802 cw(c2385.27,1802) R106.2@2389.08,1798.2 ; R106.2@2386.71,1796.62 ccw(c2386.71,1798.52) 2388.05,1797.17 R106.2@2389.07,1798.2
  Top Layer w12.3: C139.2@2386.71,1753.52 R106.2@2386.71,1796.62
LMK_SDI: PP22.1 R184.1 U22.20 U30.7 | length 3149.8
  Top Layer w5: U30.7@683.04,1647.44 v1(683.04,1698.44) ; v1(2450.47,2226.9) 2463.13,2214.24 2463.13,2201.9 U22.20@2465.06,2199.98
  L7 Ctrl Signal 1 w5: v1(2450.47,2226.9) 2505.58,2171.79 PP22.1@2647.94,2171.79
  Bottom Layer w5: v1(683.04,1698.44) 683.04,1676.17 683.29,1675.92 683.29,1672.02 701.38,1653.92 804.03,1653.92 813.02,1644.94 984.76,1644.94 1091.82,1537.87 1121.75,1537.87 1121.94,1538.07 1157.55,1502.45 1351.67,1502.45 1397.84,1548.63 1794.19,1548.63 1909.84,1664.28 2047.88,1664.28 2104,1720.4 2104,1852.24 2026.11,1930.13 2026.11,2077.19 2064.93,2116 2064.93,2197.06 2148.4,2280.54 2538.39,2280.54 2647.13,2171.79 PP22.1@2647.94,2171.79 R184.1@2697.94,2171.79
LMK_SDO: PP23.1 R185.1 U22.58 U30.9 | length 3760.2
  Top Layer w5: v1(667.29,1392.03) U30.9@667.29,1423.03 ; U22.58@2406,1853.52 2406,1834.35 2493.17,1747.18 2654.02,1747.18 2729.43,1822.59 2729.43,2040.31 PP23.1@2647.94,2121.79
  Bottom Layer w5: v1(667.29,1392.03) 667.29,1360.67 764.78,1263.18 937.62,1263.18 1081.86,1407.42 1081.86,1453.52 1112.79,1484.45 1359.12,1484.45 1405.3,1530.63 1801.65,1530.63 1917.3,1646.28 2055.34,1646.28 2122,1712.94 2122,1859.7 2044.11,1937.59 2044.11,2000 2085.64,2041.53 2113,2068.89 2113,2136.36 2140.69,2164.05 2140.69,2193.89 2209.33,2262.54 2340.76,2262.54 2369.08,2234.22 2369.08,2149.89 2388.96,2130.02 2627.01,2130.02 2628.35,2128.68 2641.05,2128.68 PP23.1@2647.94,2121.79 R185.1@2697.94,2121.79
NetC1_1: C1.1 T2.1 | length 106.7
  Top Layer w12.3: T2.1@3233.19,446.28 3233.19,469.38 cw(c3281.85,469.38) 3247.45,503.79 ccw(c3222.91,528.32) 3257.61,528.32 C1.1@3257.61,546.41
NetC1_2: C1.2 C52.2 R4.2 | length 20.4
  Top Layer w12.3: C1.2@3257.61,568.46 R4.2@3257.61,588.86
NetC2_1: "J1. "@3482.6,75 C2.1 C17.1 R2.1 | length 141.4
  Top Layer w12.3: 3482.6,72.62 C2.1@3482.6,214.04
NetC2_2: C2.2 T2.8 | length 337.2
  Top Layer w12.3: T2.8@3207.6,324.23 3207.6,274.57 ccw(c3268.13,274.57) 3268.13,214.04 C2.2@3460.55,214.04
NetC3_1: C3.1 T2.3 | length 106.7
  Top Layer w12.3: C3.1@3157.6,546.41 3157.6,528.32 ccw(c3192.29,528.32) 3167.76,503.79 cw(c3133.35,469.38) 3182.01,469.38 T2.3@3182.01,446.28
NetC3_2: C3.2 C60.2 R6.2 | length 20.4
  Top Layer w12.3: C3.2@3157.6,568.46 R6.2@3157.6,588.86
NetC4_1: C4.1 T6.3 | length 106.7
  Top Layer w12.3: T6.3@3233.19,2269.3 3233.19,2246.2 ccw(c3281.85,2246.2) 3247.45,2211.79 cw(c3222.91,2187.25) 3257.61,2187.25 C4.1@3257.61,2169.17
NetC4_2: C4.2 C61.2 R14.2 | length 20.4
  Top Layer w12.3: R14.2@3257.61,2126.72 C4.2@3257.61,2147.12
NetC5_1: "J3. "@3482.6,2641.53 C5.1 C22.1 R12.1 | length 141.4
  Top Layer w12.3: C22.1@3482.6,2501.53 3482.6,2642.95
NetC5_2: C5.2 T6.8 | length 337.2
  Top Layer w12.3: T6.8@3207.6,2391.34 3207.6,2441.01 cw(c3268.13,2441.01) 3268.13,2501.54 C5.2@3460.55,2501.53
NetC6_1: C6.1 T6.1 | length 106.7
  Top Layer w12.3: C6.1@3157.6,2169.17 3157.6,2187.25 cw(c3192.29,2187.25) 3167.76,2211.79 ccw(c3133.35,2246.2) 3182.01,2246.2 T6.1@3182.01,2269.3
NetC6_2: C6.2 C62.2 R16.2 | length 20.4
  Top Layer w12.3: R16.2@3157.6,2126.72 C6.2@3157.6,2147.12
NetC7_1: C7.1 D2.1 F2.4 Q1.1 Q1.2 Q1.5 Q1.6 Q1.8
NetC7_2: C7.2 D2.2 F2.2 Q1.3 SW1.1
NetC10_2: C10.2 R21.1 R23.2 U2.2
NetC11_2: C11.2 U2.1
NetC16_1: C16.1 C52.1 T7.4 | length 299.1
  Bottom Layer w12.1: v1(3228.47,568.46) 3229.6,569.59 3240.01,569.59 3272.49,602.07 3326.09,602.07 3409.43,518.74 3409.43,499.68 3409.68,499.43 C16.1@3410,499.43 T7.4@3410,449.43
NetC17_2: C17.2 T7.3 | length 184.9
  Top Layer w12.1: C17.2@3506.48,214.04 v1(3513.57,214.04)
  Bottom Layer w12.1: T7.3@3410,324.23 3410,297.85 ccw(c3424.52,297.85) 3424.52,283.33 3444.28,283.33 cw(c3444.28,248.67) 3478.94,248.67 ccw(c3513.57,248.67) v1(3513.57,214.04)
NetC18_1: C18.1 C60.1 T7.6 | length 298.7
  Top Layer w12.1: C60.1@3178.99,568.46 v1(3186.73,568.46) v1@3187.39,568.46
  Bottom Layer w12.1: v1(3186.73,568.46) 3162.33,568.46 3153.6,559.73 3153.6,532.95 3166.38,520.18 3299.61,520.18 3308.96,510.82 3308.96,499.68 3309.21,499.43 C18.1@3310,499.43 T7.6@3310,449.43
NetC21_1: C21.1 C61.1 T8.6 | length 307.5
  Top Layer w12.1: v1@3227.82,2147.12 v1(3228.47,2147.12) 3235.56,2147.12 C61.1@3236.22,2147.12
  Bottom Layer w12.1: v1@3226.64,2147.12 3227.77,2145.99 3238.17,2145.99 3270.66,2113.5 3324.26,2113.5 3407.59,2196.84 3407.59,2215.9 3407.84,2216.15 C21.1@3408.16,2216.15 T8.6@3408.16,2266.15
NetC22_2: C22.2 T8.3 | length 300.8
  Top Layer w12.1: C22.2@3504.65,2501.53 v1(3511.74,2501.53)
  Bottom Layer w12.1: T8.3@3308.16,2391.34 3308.16,2430.02 cw(c3321.63,2430.02) 3321.63,2443.49 ccw(c3321.63,2457.46) 3335.6,2457.46 3335.6,2482.16 cw(c3354.97,2482.16) 3354.97,2501.53 v1(3511.74,2501.53)
NetC23_2: "U6. "@1163.51,2530 "U6. "@1212.24,2525.57 C23.2 C24.2 C25.2 FB1.1 U6.10 U6.11 U6.12 U6.15 U6.27
NetC27_2: C27.2 U6.21 | length 64.7
  Top Layer w8: C27.2@959.13,2495.63 964.91,2489.84 975.97,2489.84 997.88,2467.93 1011.02,2467.93 U6.21@1011.94,2467.01
NetC28_1: C28.1 C62.1 T8.4 | length 298.7
  Top Layer w12.1: C62.1@3179.64,2147.12 3180.3,2147.12 v1(3187.39,2147.12) v1@3188.05,2147.12
  Bottom Layer w12.1: v1@3184.89,2147.12 3160.49,2147.12 3151.77,2155.85 3151.77,2182.62 3164.54,2195.4 3297.77,2195.4 3307.13,2204.75 3307.13,2215.9 3307.38,2216.15 3308.16,2216.15 T8.4@3308.16,2266.15
NetC31_1: C31.1 J7.1 R34.2 | length 222.9
  Top Layer w12.1: J7.1@1799.06,2530.98 R34.2@1998.94,2530.98 C31.1@2021.93,2530.98
NetC31_2: C31.2 U22.37 | length 574.1
  Top Layer w12.1: C31.2@2043.98,2530.98 2054.41,2530.98 cw(c2054.41,2516.13) 2069.25,2516.13 2069.25,2128.55 ccw(c2102.16,2128.55) 2102.16,2095.65 U22.37@2203.25,2095.65
NetC32_1: C32.1 J8.1 R43.2 | length 222.9
  Top Layer w12.1: C32.1@2176.19,2530.98 R43.2@2199.06,2530.98 J8.1@2399.06,2530.98
NetC32_2: C32.2 U22.34 | length 448.6
  Top Layer w12.1: C32.2@2154.15,2530.98 2143.72,2530.98 ccw(c2143.72,2516.13) 2128.88,2516.13 2128.88,2203.46 ccw(c2177.63,2203.46) 2177.63,2154.7 U22.34@2203.25,2154.7
NetC35_2: "U8. "@349.16,950.35 "U8. "@397.88,945.92 C35.2 C36.2 C37.2 FB2.1 U8.10 U8.11 U8.12 U8.15 U8.27
NetC38_2: C38.2 FB2.2 FC3.1 PP4.1 R48.2 | length 563.2
  Bottom Layer w8: v1(105.4,881.98) 181.68,881.98 231.54,931.84 634.35,931.84 643.74,922.45 v1(644.03,922.45)
NetC41_2: C41.2 U8.21 | length 64.7
  Top Layer w8: C41.2@144.77,915.98 150.55,910.2 161.61,910.2 183.52,888.28 196.66,888.28 U8.21@197.58,887.36
NetC43_1: C43.1 R87.1 R90.2 U18.4 | length 115.4
  Top Layer w8: C43.1@1280.62,1987.52 1280.62,1988.31 1282.92,1990.6 1283.71,1990.6 1289.28,1996.18 R87.1@1310.62,1996.18 1343.65,1996.18 1351.46,2003.99 1361,2003.99 1368.51,2011.49 U18.4@1385.62,2011.49
NetC45_2: C45.2 R54.1 R55.2 U9.10 U10.9 U10.10 | length 76.6
  Bottom Layer w10: v1(1108.11,1149.17) 1123.73,1149.17 1138.3,1134.6 1138.3,1095.46 U9.10@1139.21,1094.56
NetC49_2: C49.2 R56.2 U10.7 | length 44
  Top Layer w9: U10.7@972.11,1098.78 1006.76,1098.78 1012.11,1093.44 R56.2@1012.11,1091.69
NetC53_1: C53.1 FB4.2
NetC58_1: C58.1 U11.10 | length 29.7
  Top Layer w8: C58.1@1035.54,1593.61 cw(c1036.72,1593.61) 1036.72,1594.79 U11.10@1064.54,1594.79
NetC58_2: C58.2 U11.9 | length 29.7
  Top Layer w8: C58.2@1035.54,1615.66 ccw(c1036.72,1615.66) 1036.72,1614.48 U11.9@1064.54,1614.48
NetC59_2: C59.2 FC7.1 R59.2 U11.6
NetC63_2: C63.2 U11.5 | length 52.1
  Top Layer w8: U11.5@1139.34,1634.16 1174.42,1634.16 ccw(c1174.42,1644.99) C63.2@1185.25,1644.99
NetC66_1: C66.1 U13.10 | length 29.7
  Top Layer w8: U13.10@1648.76,1727.65 1676.58,1727.65 ccw(c1676.58,1728.83) C66.1@1677.76,1728.83
NetC66_2: C66.2 U13.9 | length 29.7
  Top Layer w8: U13.9@1648.76,1707.96 1676.58,1707.96 cw(c1676.58,1706.78) C66.2@1677.76,1706.78
NetC67_2: C67.2 FC8.1 R64.2 U13.6
NetC71_2: C71.2 U13.5 | length 52.1
  Top Layer w8: C71.2@1528.05,1677.45 cw(c1538.88,1677.45) 1538.88,1688.28 U13.5@1573.96,1688.28
NetC75_2: C75.2 R71.1 R72.2 U14.10 U15.9 U15.10 | length 136.8
  Bottom Layer w10: v1(1204.61,689.21) 1220.23,689.21 1234.8,674.63 1234.8,655.07 cw(c1234.8,654.16) 1235.71,654.16 U14.10@1235.71,574.59
NetC79_2: C79.2 R73.2 U15.7 | length 44
  Top Layer w9: U15.7@1068.61,638.78 1103.26,638.78 1108.61,633.44 R73.2@1108.61,631.69
NetC82_2: C82.2 R79.1 R80.2 U16.10 U17.9 U17.10 | length 136.8
  Bottom Layer w10: v1(1204.61,939.21) 1220.23,939.21 1234.8,924.63 1234.8,905.07 cw(c1234.8,904.16) 1235.71,904.16 U16.10@1235.71,824.59
NetC83_2: C83.2 C109.2 C110.2 C111.2 FB6.2 FC10.1 PP16.1
NetC85_2: C85.2 R81.2 U17.7 | length 44
  Top Layer w9: U17.7@1068.61,888.78 1103.26,888.78 1108.61,883.44 R81.2@1108.61,881.69
NetC90_1: C90.1 U18.13 | length 41.5
  Top Layer w8: C90.1@1418.67,2111.94 1419.46,2111.94 1421.76,2109.64 1421.76,2108.86 1433.36,2097.26 U18.13@1433.36,2076.94
NetC90_2: C90.2 U18.14 | length 42.6
  Top Layer w8: C90.2@1396.63,2111.94 1397.41,2111.94 1399.71,2109.64 1399.71,2108.86 1403.59,2104.98 1403.59,2102.33 1408.27,2097.64 1408.37,2097.64 1413.05,2092.96 1413.05,2077.56 U18.14@1413.67,2076.94
NetC96_2: C96.2 U18.6 | length 78.3
  Top Layer w8: C96.2@1393.67,1915.42 1393.67,1945.72 1413.67,1965.72 U18.6@1413.67,1985.41
NetC99_1: C99.1 C100.1 | length 351.7
  Top Layer w12.3: C99.1@2736.38,975.31 2847.76,975.31 ccw(c2847.76,1075.31) 2947.76,1075.31 C100.1@2947.76,1158.58
NetC99_2: C99.2 C101.2 J6.1 | length 175
  Top Layer w12.1: J6.1@2539.47,975.31 C101.2@2714.47,975.31
NetC100_2: C100.2 C102.1 U1.D16 | length 122
  Top Layer w12.3: C102.1@2947.76,1180.62 U1.D16@3069.81,1180.62
NetC101_1: C101.1 T9.8 | length 233.8
  Top Layer w12.3: C101.1@2714.47,997.35 2714.47,1180.79 cw(c2733.98,1180.79) 2733.98,1200.31 T9.8@2753.67,1200.31
NetC102_2: C102.2 T9.1 | length 52.4
  Top Layer w12.3: T9.1@2875.71,1174.72 2903.3,1174.72 2909.2,1180.62 C102.2@2925.71,1180.62
NetC103_1: C103.1 C104.2 U1.E16 | length 122.2
  Top Layer w12.3: C104.2@2947.63,1219.99 U1.E16@3069.81,1219.99
NetC103_2: C103.2 T9.3 | length 52.4
  Top Layer w12.3: T9.3@2875.71,1225.9 2903.3,1225.9 2909.2,1219.99 C103.2@2925.71,1219.99
NetC104_1: C104.1 C105.1 | length 351.7
  Top Layer w12.3: C105.1@2736.38,1425.31 2847.76,1425.31 cw(c2847.76,1325.31) 2947.76,1325.31 C104.1@2947.76,1242.04
NetC105_2: C105.2 J11.1 | length 175
  Top Layer w12.1: J11.1@2539.47,1425.31 C105.2@2714.47,1425.31
NetC106_1: C106.1 J14.1 | length 211.7
  Top Layer w12.1: J14.1@2075,1655.63 2075,1695.5 2090.51,1711.01 2207.73,1711.01 2219.07,1722.35 C106.1@2219.07,1739.03
NetC106_2: C106.2 R37.2 U22.51 | length 123.8
  Top Layer w12.1: C106.2@2219.07,1761.07 R37.2@2219.07,1784.07 2219.07,1807.29 2233.9,1822.12 2252.68,1822.12 2268.21,1837.64 U22.51@2268.21,1853.52
NetC107_1: C107.1 R91.2 | length 21
  Top Layer w12.1: R91.2@2243.6,1718.03 C107.1@2243.6,1739.03
NetC107_2: C107.2 R38.2 U22.52 | length 122.4
  Top Layer w12.1: C107.2@2243.6,1761.07 R38.2@2243.6,1784.07 2244.39,1784.07 2248.51,1788.2 2248.51,1794.53 2257.1,1803.12 2276.2,1803.12 2287.89,1814.81 U22.52@2287.89,1853.52
NetC127_2: C127.2 U22.38 | length 32.1
  Top Layer w12.3: C127.2@2173.25,2070.96 2174.03,2070.96 2179.03,2075.96 U22.38@2203.25,2075.96
NetC128_2: C128.2 U22.35 | length 32.1
  Top Layer w12.3: C128.2@2173.25,2130.02 2174.03,2130.02 2179.03,2135.02 U22.35@2203.25,2135.02
NetC144_2: C144.2 U22.11 | length 27.1
  Top Layer w10: U22.11@2549.7,2075.96 2567.54,2075.96 2572.54,2070.96 v1(2574.7,2070.96)
NetC145_2: C145.2 U22.12
  other v1: 2549.7,2095.65
NetC146_2: C146.2 C147.2 FB7.2 U24.9
NetC153_2: C153.2 C154.2 FB8.2 U24.4
NetC159_2: C159.2 U24.2 Y1.1 | length 338.6
  Top Layer w5: Y1.1@304.27,2402.82 309.27,2397.82 358.63,2397.82 363.63,2402.82 383.77,2402.82 473.44,2313.16 473.44,2289.34 467.54,2283.43 U24.2@428.16,2283.43
  Top Layer w8: C159.2@264.27,2362.82 Y1.1@304.27,2402.82
NetC160_2: C160.2 U24.3 Y1.2 | length 411.4
  Top Layer w5: Y1.2@418.41,2516.96 423.41,2511.96 423.41,2462.6 399.06,2438.25 399.06,2400.27 487.77,2311.56 487.77,2275.56 475.96,2263.75 U24.3@428.16,2263.75
  Top Layer w8: Y1.2@418.41,2516.96 C160.2@458.41,2556.96
NetC172_1: C172.1 R149.1 U1.J15 | length 103.4
  Bottom Layer w5: R149.1@3030.44,1412.79 3032.41,1412.79 3039.75,1405.45 3039.75,1403.48 3045.98,1397.24 3077.93,1397.24 3078.2,1397.52 3089.13,1397.52 v1(3109.18,1377.47) C172.1@3109.18,1368.81
NetD3_2: D3.2 R24.2 | length 50
  Top Layer w12: D3.2@1614.31,471.85 v1(1664.31,471.85)
NetD5_1: D5.1 R191.1
  other v1: 4241.78,111.32
NetD5_2: D5.2 U33.4 | length 54.9
  Bottom Layer w12: U33.4@4195.01,150.69 4222.09,150.69 v1(4241.78,170.37)
NetF1_2: F1.2 R21.2 SW1.2 U2.3 U2.4 U2.5
NetF2_1: F2.1 J5.1 TP4.1
NetF2_3: F2.3 J5.2 J5.3 TP5.1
